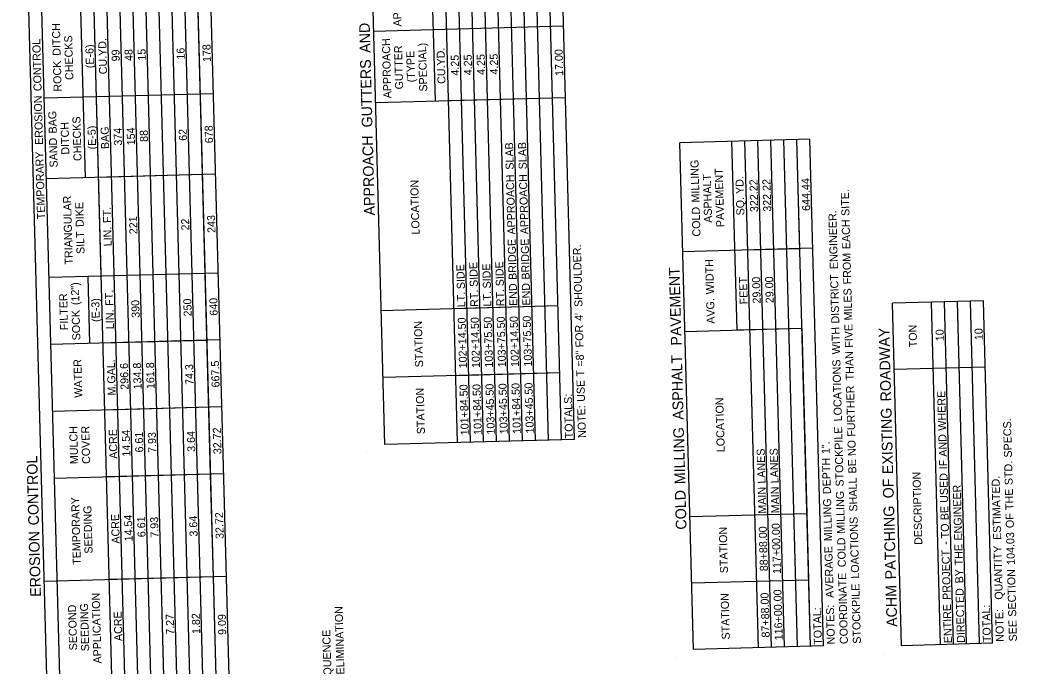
# Model space of a CAD drawing. Extents: x 1930091 to 1931962, y 596452 to 607874.
# Drawn here: x 1930332 to 1931079, y 599740 to 600225 of the extents above; entities that cross this region are included whole.
import ezdxf

# ---------------------------------------------------------------- set-up
doc = ezdxf.new("R2010")
doc.units = 0
doc.layers.add('Default', color=7, linetype='Continuous')
doc.layers.add('R_Border', color=7, linetype='Continuous')

msp = doc.modelspace()

# ---------------------------------------------------------------- linework, layer by layer
at = {"layer": 'Default'}
for p, q in [((1930365.9, 599209.42), (1930331.67, 600484.26)), ((1930366.93, 599534.24), (1930341.42, 600484.52)), ((1930405.92, 599535.29), (1930380.41, 600485.57)), ((1930424.37, 599210.99), (1930390.15, 600485.83)), ((1930434.12, 599211.25), (1930399.9, 600486.09)), ((1930443.87, 599211.51), (1930409.65, 600486.35)), ((1930453.61, 599211.78), (1930419.39, 600486.62)), ((1930463.36, 599212.04), (1930429.14, 600486.88)), ((1930473.11, 599212.3), (1930438.88, 600487.14)), ((1930482.85, 599212.56), (1930448.63, 600487.4)), ((1930492.6, 599212.82), (1930458.38, 600487.66)), ((1930502.35, 599213.08), (1930468.12, 600487.92)), ((1930698.74, 599909.07), (1930684.51, 600439.28)), ((1930708.49, 599909.33), (1930694.26, 600439.54)), ((1930718.24, 599909.59), (1930704, 600439.8)), ((1930727.98, 599909.85), (1930713.75, 600440.06)), ((1930737.73, 599910.11), (1930723.5, 600440.32)), ((1930747.47, 599910.37), (1930733.24, 600440.58)), ((1930605.18, 599906.55), (1930590.94, 600436.76)), ((1930643.13, 600164.09), (1930635.78, 600437.97)), ((1930659.76, 599908.02), (1930645.52, 600438.23)), ((1930669.5, 599908.28), (1930655.27, 600438.49)), ((1930679.25, 599908.54), (1930665.02, 600438.75)), ((1930689, 599908.8), (1930674.76, 600439.01)), ((1930380.82, 600106.66), (1930374.05, 600359.09)), ((1930392.56, 600032.85), (1930383.79, 600359.35)), ((1930474.57, 599884.36), (1930465.27, 600230.84)), ((1930739.15, 600220.31), (1930596.86, 600216.49)), ((1930739.15, 600220.31), (1930641.69, 600217.7)), ((1930476.67, 600169.7), (1930349.96, 600166.3)), ((1930466.92, 600169.44), (1930388.95, 600167.35)), ((1930740.59, 600166.71), (1930598.3, 600162.89)), ((1930740.59, 600166.71), (1930652.88, 600164.35)), ((1930923.86, 600135.63), (1930826.4, 600133.01)), ((1930923.86, 600135.63), (1930826.4, 600133.01)), ((1930836.6, 599752.9), (1930826.4, 600133.01)), ((1930869.19, 599992.25), (1930865.39, 600134.06)), ((1930885.34, 599754.21), (1930875.13, 600134.32)), ((1930895.08, 599754.47), (1930884.88, 600134.58)), ((1930904.83, 599754.73), (1930894.62, 600134.85)), ((1930914.57, 599754.99), (1930904.37, 600135.11)), ((1930924.32, 599755.26), (1930914.12, 600135.37)), ((1930916.32, 600053.5), (1930914.12, 600135.37)), ((1930934.07, 599755.52), (1930923.86, 600135.63)), ((1930478.29, 600109.27), (1930351.58, 600105.87)), ((1930468.54, 600109.01), (1930390.57, 600106.92)), ((1930926.06, 600053.76), (1930828.6, 600051.14)), ((1930916.32, 600053.5), (1930877.33, 600052.45)), ((1930480.28, 600035.2), (1930353.57, 600031.8)), ((1930384.16, 599982.39), (1930382.81, 600032.58)), ((1930470.53, 600034.94), (1930392.56, 600032.85)), ((1931053.86, 600014.33), (1930985.64, 600012.5)), ((1931053.86, 600014.33), (1931014.88, 600013.28)), ((1931021.77, 599756.46), (1931014.88, 600013.28)), ((1931031.52, 599756.72), (1931024.62, 600013.54)), ((1931041.27, 599756.98), (1931034.37, 600013.8)), ((1931051.01, 599757.25), (1931044.12, 600014.07)), ((1931060.76, 599757.51), (1931053.86, 600014.33)), ((1930735.03, 600010.5), (1930602.48, 600006.94)), ((1930735.03, 600010.5), (1930657.06, 600008.41)), ((1930992.53, 599755.68), (1930985.64, 600012.5)), ((1930917.92, 599993.56), (1930830.21, 599991.2)), ((1930917.92, 599993.56), (1930869.19, 599992.25)), ((1930921.65, 599854.67), (1930917.92, 599993.56)), ((1930481.62, 599985.01), (1930354.92, 599981.6)), ((1930471.88, 599984.74), (1930393.91, 599982.65)), ((1931055.2, 599964.62), (1930986.97, 599962.79)), ((1931055.2, 599964.62), (1931016.21, 599963.57)), ((1930736.38, 599960.31), (1930603.83, 599956.75)), ((1930736.38, 599960.31), (1930658.41, 599958.21)), ((1930482.97, 599934.81), (1930356.27, 599931.41)), ((1930482.97, 599934.81), (1930395.25, 599932.46)), ((1930747.47, 599910.37), (1930605.18, 599906.55)), ((1930747.47, 599910.37), (1930605.18, 599906.55)), ((1930484.32, 599884.62), (1930357.61, 599881.22)), ((1930484.32, 599884.62), (1930396.6, 599882.26)), ((1930476.64, 599807.36), (1930474.57, 599884.36)), ((1930921.65, 599854.67), (1930833.93, 599852.32)), ((1930921.65, 599854.67), (1930882.67, 599853.62)), ((1930922.99, 599804.96), (1930921.65, 599854.67)), ((1930486.39, 599807.62), (1930349.94, 599803.96)), ((1930359.68, 599804.22), (1930349.94, 599803.96)), ((1930476.64, 599807.36), (1930398.67, 599805.26)), ((1930482.54, 599587.57), (1930476.64, 599807.36)), ((1930922.99, 599804.96), (1930835.27, 599802.61)), ((1930922.99, 599804.96), (1930884, 599803.92)), ((1930924.32, 599755.26), (1930922.99, 599804.96)), ((1930934.07, 599755.52), (1930836.6, 599752.9)), ((1930934.07, 599755.52), (1930836.6, 599752.9)), ((1931060.76, 599757.51), (1930992.53, 599755.68)), ((1931060.76, 599757.51), (1930992.53, 599755.68))]:
    msp.add_line(p, q, dxfattribs=at)
at = {"layer": 'R_Border'}
for p, q in [((1930591.69, 599900.34), (1930591.69, 599900.34)), ((1930823.11, 599746.69), (1930823.11, 599746.69)), ((1930979.04, 599749.46), (1930979.04, 599749.46))]:
    msp.add_line(p, q, dxfattribs=at)

# ---------------------------------------------------------------- texts
at = {"layer": 'Default'}
for s, height, p in [('APPROACH', 6, (1930617.69, 600220.2)), (' AND', 8, (1930594.54, 600197.51)), (' DITCH', 6, (1930362.29, 600196.04)), (' CONTROL', 6, (1930348, 600169.5)), ('CHECKS', 6, (1930371.72, 600180.1)), ('CU.YD.', 6, (1930397.04, 600184.36)), ('APPROACH', 6, (1930610.13, 600166.35)), ('SPECIAL)', 6, (1930637.01, 600171.4)), ('(E-6)', 6, (1930387.17, 600188.93)), ('99', 6, (1930406.54, 600194.07)), ('48', 6, (1930416.28, 600194.33)), ('15', 6, (1930426.03, 600194.57)), ('16', 6, (1930455.27, 600195.38)), ('178', 6, (1930474.83, 600193.57)), ('GUTTER', 6, (1930618.96, 600173.04)), ('(TYPE', 6, (1930627.82, 600178.36)), ('CU.YD.', 6, (1930650.66, 600177.19)), ('17.00', 6, (1930738.95, 600183.2)), ('ROCK', 6, (1930362.96, 600171.38)), (' GUTTERS', 8, (1930596.04, 600141.56)), ('4.25', 6, (1930660.92, 600183.4)), ('4.25', 6, (1930670.66, 600183.66)), ('4.25', 6, (1930680.41, 600183.92)), ('4.25', 6, (1930690.16, 600184.19)), (' EROSION', 6, (1930349.08, 600129.19)), (' BAG', 6, (1930359.36, 600137.76)), ('DITCH', 6, (1930368.73, 600124.08)), ('CHECKS', 6, (1930377.86, 600119.31)), ('(E-5)', 6, (1930388.8, 600128.01)), ('BAG', 6, (1930398.55, 600128.3)), ('374', 6, (1930408.23, 600130.84)), ('154', 6, (1930417.98, 600131.1)), ('88', 6, (1930427.67, 600133.67)), ('62', 6, (1930456.9, 600134.5)), ('678', 6, (1930476.46, 600132.66)), ('SAND', 6, (1930359.98, 600114.43)), ('APPROACH', 8, (1930597.74, 600078.47)), (' SLAB', 6, (1930701.89, 600110.61)), (' SLAB', 6, (1930711.63, 600110.87)), ('TEMPORARY', 6, (1930350.52, 600075.63)), (' MILLING', 6, (1930841.17, 600085.97)), ('PAVEMENT', 6, (1930859.61, 600069.73)), ('LOCATION', 6, (1930631.26, 600064.18)), (' APPROACH', 6, (1930703.19, 600061.92)), (' APPROACH', 6, (1930712.94, 600062.18)), ('ASPHALT', 6, (1930850.52, 600072.98)), (' YD.', 6, (1930874.38, 600092.41)), ('322.22', 6, (1930885.12, 600081.03)), ('322.22', 6, (1930894.86, 600081.29)), ('644.44', 6, (1930924.1, 600081.95)), (' SITE.', 6, (1930953.53, 600075.88)), ('TRIANGULAR', 6, (1930371.31, 600041.64)), (' DIKE', 6, (1930379.62, 600067.59)), ('SQ.', 6, (1930874.75, 600078.55)), (' FT.', 6, (1930400.1, 600070.58)), ('COLD', 6, (1930841.79, 600062.64)), (' ENGINEER.', 6, (1930944.85, 600036)), ('221', 6, (1930419.77, 600064.42)), ('22', 6, (1930458.71, 600067.24)), ('243', 6, (1930478.27, 600065.4)), (' EACH', 6, (1930954.2, 600050.95)), ('SILT', 6, (1930380.1, 600049.6)), ('LIN.', 6, (1930400.51, 600055.33)), (' BRIDGE', 6, (1930704.11, 600027.91)), (' BRIDGE', 6, (1930713.85, 600028.17)), ('  SHOULDER.', 6, (1930753.48, 600005.4)), (' SIDE', 6, (1930674.99, 600022.64)), (' SIDE', 6, (1930694.48, 600023.17)), (' WIDTH', 6, (1930852.02, 600017.16)), (' FROM', 6, (1930954.91, 600024.58)), (' SIDE', 6, (1930665.28, 600020.99)), (' SIDE', 6, (1930684.77, 600021.51)), (' PAVEMENT', 8, (1930827.74, 599977.95)), ('FEET', 6, (1930877.22, 600011.83)), ('29.00', 6, (1930886.96, 600012.43)), ('29.00', 6, (1930896.7, 600012.69)), (' DISTRICT', 6, (1930945.94, 599995.2)), (' (12")', 6, (1930376.32, 600009.02)), (' FT.', 6, (1930401.77, 600008.44)), ('RT.', 6, (1930675.33, 600009.87)), ('LT.', 6, (1930685.08, 600010.14)), ('RT.', 6, (1930694.82, 600010.4)), ('END', 6, (1930704.57, 600010.66)), ('END', 6, (1930714.31, 600010.92)), (' MILES', 6, (1930955.63, 599997.54)), ('FILTER', 6, (1930367.76, 599992.41)), ('(E-3)', 6, (1930391.6, 599998.61)), ('390', 6, (1930421.45, 600001.71)), ('250', 6, (1930460.44, 600002.76)), ('640', 6, (1930479.93, 600003.29)), ('LT.', 6, (1930665.58, 600009.61)), ('AVG.', 6, (1930852.55, 599997.25)), ('SOCK', 6, (1930376.97, 599984.81)), ('LIN.', 6, (1930402.18, 599993.19)), ('STATION', 6, (1930633.93, 599964.6)), ('102+14.50', 6, (1930666.81, 599963.83)), ('102+14.50', 6, (1930676.56, 599964.09)), ('103+75.50', 6, (1930686.3, 599964.35)), ('103+75.50', 6, (1930696.05, 599964.61)), ('102+14.50', 6, (1930705.8, 599964.88)), ('103+75.50', 6, (1930715.54, 599965.14)), (" 4'", 6, (1930753.7, 599997.21)), (' FOR', 6, (1930754.23, 599977.31)), (' WITH', 6, (1930946.56, 599972.14)), (' FIVE', 6, (1930956.18, 599977.03)), (' ROADWAY', 8, (1930984.86, 599936.06)), ('TON', 6, (1931004.15, 599979.6)), ('10', 6, (1931024.21, 599984.2)), ('10', 6, (1931053.45, 599984.99)), (' =8"', 6, (1930754.62, 599962.85)), (' THAN', 6, (1930956.84, 599952.58)), ('WATER', 6, (1930378.5, 599941.77)), ('M.GAL.', 6, (1930403.51, 599943.41)), ('667.5', 6, (1930481.38, 599949.52)), (' ASPHALT', 8, (1930829.23, 599922.31)), (' LOCATIONS', 6, (1930947.91, 599921.82)), ('296.6', 6, (1930413.15, 599947.75)), ('134.8', 6, (1930422.9, 599948.01)), ('161.8', 6, (1930432.64, 599948.27)), ('74.3', 6, (1930461.82, 599951.39)), (' T', 6, (1930754.81, 599955.57)), (' USE', 6, (1930755.33, 599936.46)), ('STATION', 6, (1930635.28, 599914.41)), ('101+84.50', 6, (1930668.16, 599913.63)), ('101+84.50', 6, (1930677.91, 599913.9)), ('103+45.50', 6, (1930687.65, 599914.16)), ('103+45.50', 6, (1930697.4, 599914.42)), ('101+84.50', 6, (1930707.14, 599914.68)), ('103+45.50', 6, (1930716.89, 599914.94)), (' FURTHER', 6, (1930957.97, 599910.32)), (' WHERE', 6, (1931026.07, 599914.87)), ('TOTALS:', 6, (1930746.25, 599911.32)), ('LOCATION', 6, (1930860.01, 599900.95)), ('NOTE:', 6, (1930756, 599911.58)), (' EXISTING', 8, (1930986.33, 599881.47)), (' SPECS.', 6, (1931075.38, 599894.67)), ('MULCH', 6, (1930375.33, 599891.99)), ('COVER', 6, (1930384.33, 599892.15)), ('ACRE', 6, (1930404.79, 599895.92)), ('14.54', 6, (1930414.5, 599897.57)), ('6.61', 6, (1930424.17, 599900.73)), ('3.64', 6, (1930463.17, 599901.21)), ('32.72', 6, (1930482.72, 599899.41)), (' MILLING', 8, (1930830.53, 599873.95)), (' STOCKPILE', 6, (1930949.22, 599872.9)), ('7.93', 6, (1930433.93, 599900.41)), (' NO', 6, (1930958.36, 599895.8)), (' AND', 6, (1931026.6, 599895.29)), (' LANES', 6, (1930890.64, 599875.09)), (' LANES', 6, (1930900.39, 599875.35)), (' 1".', 6, (1930938.81, 599897.31)), (' CONTROL', 8, (1930346.06, 599843.08)), (' DEPTH', 6, (1930939.62, 599867.25)), (' BE', 6, (1930958.71, 599882.74)), (' IF', 6, (1931026.85, 599885.9)), (' STD.', 6, (1931075.94, 599873.98)), (' SHALL', 6, (1930959.48, 599854.16)), (' OF', 8, (1930986.82, 599863.37)), ('DESCRIPTION', 6, (1931008.13, 599831.4)), (' USED', 6, (1931027.53, 599860.73)), (' ESTIMATED.', 6, (1931067.29, 599832.88)), ('COLD', 8, (1930831.36, 599842.85)), ('MAIN', 6, (1930891.19, 599854.83)), ('MAIN', 6, (1930900.93, 599855.09)), (' MILLING', 6, (1930950.17, 599837.57)), (' ENGINEER', 6, (1931038.04, 599832.41)), (' THE', 6, (1931076.44, 599855.34)), ('TEMPORARY', 6, (1930377.36, 599816.42)), (' MILLING', 6, (1930940.57, 599831.92)), ('SEEDING', 6, (1930386.14, 599824.83)), (' PATCHING', 8, (1930988.45, 599802.59)), (' BE', 6, (1931027.88, 599847.67)), ('ACRE', 6, (1930406.49, 599832.33)), ('14.54', 6, (1930416.2, 599833.98)), ('6.61', 6, (1930425.87, 599837.14)), ('7.93', 6, (1930435.63, 599836.82)), ('3.64', 6, (1930464.87, 599837.62)), ('32.72', 6, (1930484.43, 599835.82)), (' LOACTIONS', 6, (1930960.83, 599803.84)), (' OF', 6, (1931076.8, 599841.76)), ('STATION', 6, (1930862.45, 599810.14)), ('88+88.00', 6, (1930892.35, 599811.62)), ('117+00.00', 6, (1930902.16, 599809.55)), (' TO', 6, (1931028.24, 599834.08)), ('EROSION', 8, (1930347.42, 599792.44)), (' COLD', 6, (1930950.85, 599812.41)), (' -', 6, (1931028.37, 599829.23)), (' 104.03', 6, (1931077.54, 599814.19)), ('  AVERAGE', 6, (1930941.77, 599787.19)), (' PROJECT', 6, (1931029.48, 599787.95)), (' THE', 6, (1931038.54, 599813.76)), ('   QUANTITY', 6, (1931068.61, 599783.59)), (' BY', 6, (1931038.9, 599800.32)), (' SECTION', 6, (1931078.59, 599775.3)), ('COORDINATE', 6, (1930952.34, 599756.98)), ('116+00.00', 6, (1930903.49, 599759.84)), ('STOCKPILE', 6, (1930962.08, 599757.25)), ('ACHM', 8, (1930989.33, 599769.87)), ('DIRECTED', 6, (1931040.04, 599757.93)), ('APPLICATION', 6, (1930392.85, 599742.4)), ('STATION', 6, (1930863.79, 599760.43)), ('87+88.00', 6, (1930893.68, 599761.91)), ('SECOND', 6, (1930374.58, 599752.26)), ('SEEDING', 6, (1930383.6, 599751.61)), (' ELIMINATION', 6, (1930575, 599731.95)), ('TOTAL:', 6, (1930932.84, 599756.46)), ('NOTES:', 6, (1930942.59, 599756.72)), ('ENTIRE', 6, (1931030.29, 599757.66)), ('TOTAL:', 6, (1931059.53, 599758.45)), ('NOTE:', 6, (1931069.28, 599758.71)), ('ACRE', 6, (1930408.46, 599759.23)), ('7.27', 6, (1930447.34, 599763.98)), ('1.82', 6, (1930466.84, 599764.53)), ('9.09', 6, (1930486.36, 599763.87)), ('SEE', 6, (1931079.03, 599758.97)), (' SEQUENCE', 6, (1930565.55, 599720.47))]:
    msp.add_text(s, height=height, rotation=91.53769, dxfattribs=at).set_placement(p)

doc.saveas('drawing.dxf')
